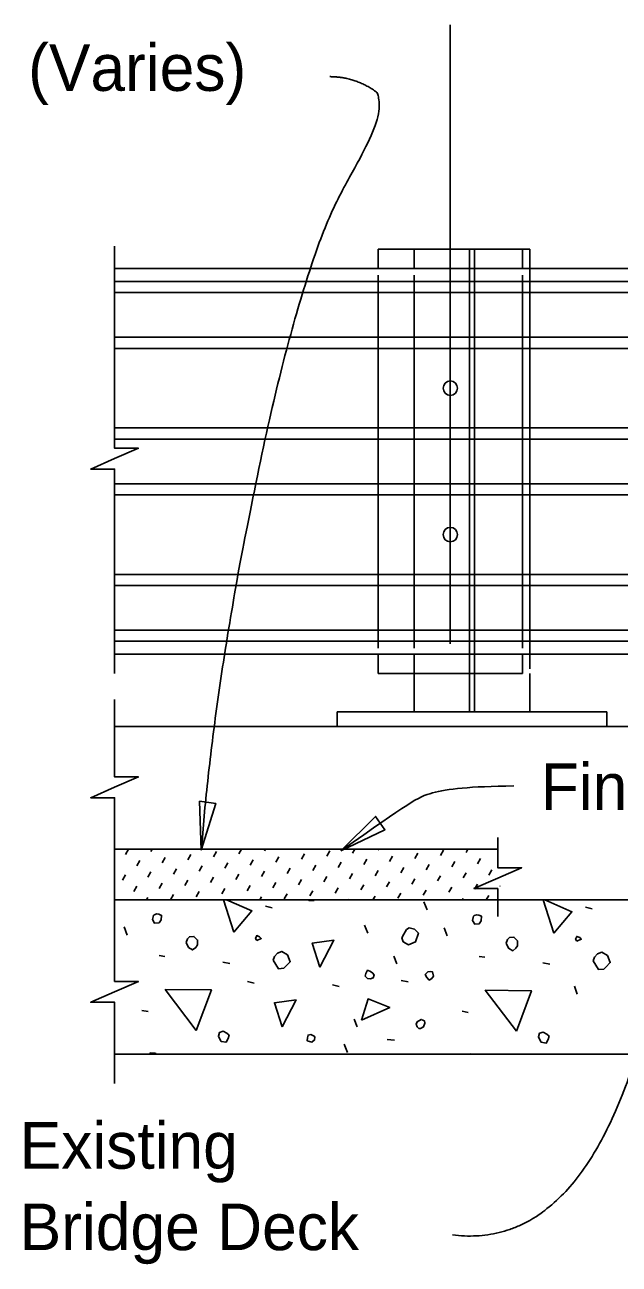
# Model space of a CAD drawing. Extents: x 21587 to 21656.3, y 56114 to 56157.2.
# Drawn here: x 21587.27 to 21589.85, y 56132.48 to 56137.83 of the extents above; entities that cross this region are included whole.
import ezdxf

# ---------------------------------------------------------------- set-up
doc = ezdxf.new("R2010")
doc.units = 0
for name, color, linetype in [('AdhocPoint_dp', 7, 'Continuous'), ('Border', 7, 'Continuous'), ('Patterning', 7, 'Continuous'), ('PlotBorder_dp', 7, 'Continuous'), ('SheetBorder_dp', 7, 'Continuous'), ('TextMisc', 7, 'Continuous')]:
    doc.layers.add(name, color=color, linetype=linetype)

msp = doc.modelspace()

# ---------------------------------------------------------------- linework, layer by layer
at = {"layer": 'AdhocPoint_dp'}
for p, q in [((21593.837, 56134.8009), (21587.6633, 56134.8009)), ((21589.3212, 56134.2699), (21587.6633, 56134.2699)), ((21587.6633, 56134.0511), (21593.837, 56134.0511)), ((21587.6633, 56133.3843), (21593.837, 56133.3843))]:
    msp.add_line(p, q, dxfattribs=at)
at = {"layer": 'Border'}
for p, q in [((21588.9596, 56136.8635), (21589.4596, 56136.8635)), ((21588.9596, 56136.8635), (21588.9596, 56136.7802)), ((21599.7592, 56136.7801), (21587.6633, 56136.7801)), ((21587.6633, 56136.7246), (21599.7592, 56136.7246)), ((21587.6633, 56136.6764), (21599.7592, 56136.6764)), ((21587.6633, 56136.4835), (21599.7592, 56136.4835)), ((21587.6633, 56136.4353), (21599.7592, 56136.4353)), ((21587.6633, 56136.0914), (21599.7592, 56136.0914)), ((21587.6633, 56136.0431), (21599.7592, 56136.0431)), ((21587.6633, 56135.8503), (21599.7592, 56135.8503)), ((21587.6633, 56135.8022), (21599.7592, 56135.8022)), ((21587.6633, 56135.4582), (21599.7592, 56135.4582)), ((21587.6633, 56135.41), (21599.7592, 56135.41)), ((21587.6633, 56135.2172), (21599.7592, 56135.2172)), ((21587.6633, 56135.169), (21599.7592, 56135.169)), ((21599.7592, 56135.1134), (21587.6633, 56135.1134)), ((21588.9596, 56135.1135), (21588.9596, 56134.8635)), ((21589.4596, 56135.0302), (21589.4596, 56134.8635)), ((21588.6263, 56134.8635), (21589.7929, 56134.8635)), ((21588.6263, 56134.801), (21588.6263, 56134.8635)), ((21588.9596, 56134.8635), (21589.4596, 56134.8635)), ((21589.7929, 56134.8635), (21589.7929, 56134.801)), ((21588.6263, 56134.801), (21589.7929, 56134.801))]:
    msp.add_line(p, q, dxfattribs=at)
for centre in [(21589.1159, 56136.2634), (21589.1159, 56135.6303)]:
    msp.add_circle(centre, 0.0312, dxfattribs=at)
at = {"layer": 'Patterning'}
for p, q in [((21589.1992, 56134.8635), (21589.1992, 56136.8635)), ((21589.22, 56134.8635), (21589.22, 56136.8635)), ((21589.4596, 56136.8635), (21589.4596, 56135.0505)), ((21588.9596, 56136.7516), (21588.9596, 56135.1398))]:
    msp.add_line(p, q, dxfattribs=at)
at = {"layer": 'PlotBorder_dp'}
msp.add_line((21589.1159, 56135.1581), (21589.1159, 56137.8341), dxfattribs=at)
for points in [[(21587.6633, 56135.0304), (21587.6633, 56135.9136), (21587.5599, 56135.9136), (21587.6633, 56135.9586), (21587.7666, 56136.0036), (21587.6633, 56136.0036), (21587.6633, 56136.8766)], [(21587.6633, 56134.023), (21587.6633, 56134.4931), (21587.5599, 56134.4931), (21587.6633, 56134.5381), (21587.7666, 56134.5831), (21587.6633, 56134.5831), (21587.6633, 56134.9176)], [(21589.3213, 56133.979), (21589.3213, 56134.0999), (21589.2179, 56134.0999), (21589.3213, 56134.1449), (21589.4246, 56134.1899), (21589.3213, 56134.1899), (21589.3213, 56134.3205)], [(21587.6633, 56133.2579), (21587.6633, 56133.6085), (21587.5599, 56133.6085), (21587.6633, 56133.6535), (21587.7666, 56133.6985), (21587.6633, 56133.6985), (21587.6633, 56134.023)]]:
    msp.add_lwpolyline(points, dxfattribs=at)
for points in [[(21588.0386, 56134.2665), (21588.1011, 56134.4682), (21588.0312, 56134.4775)], [(21588.6428, 56134.2633), (21588.8333, 56134.3544), (21588.7927, 56134.4121)]]:
    msp.add_lwpolyline(points, close=True, dxfattribs=at)
for points, degree in [([(21588.5944, 56137.6099), (21588.6936, 56137.6099), (21588.8704, 56137.4978), (21588.4823, 56136.8422), (21588.0942, 56134.9965), (21588.0386, 56134.2665)], 2), ([(21589.3913, 56134.5436), (21589.1979, 56134.5415), (21589.0095, 56134.5211), (21588.9381, 56134.4713), (21588.6427, 56134.2634)], 3), ([(21590.0017, 56133.6862), (21589.743, 56132.5258), (21589.1249, 56132.603)], 2)]:
    msp.add_open_spline(points, degree=degree, dxfattribs=at)
at = {"layer": 'TextMisc'}
for p, q in [((21588.8034, 56136.8635), (21589.4284, 56136.8635)), ((21588.8034, 56136.8635), (21588.8034, 56136.7802)), ((21589.4284, 56136.8635), (21589.4284, 56136.7802)), ((21588.8034, 56136.7516), (21588.8034, 56135.1398)), ((21589.4284, 56136.7516), (21589.4284, 56135.1398)), ((21588.8034, 56135.0302), (21588.8034, 56135.1135)), ((21589.4284, 56135.0302), (21589.4284, 56135.1135)), ((21588.8034, 56135.0302), (21589.4284, 56135.0302)), ((21587.7102, 56134.2474), (21587.7231, 56134.2698)), ((21587.8208, 56134.2604), (21587.8263, 56134.2699)), ((21587.9803, 56134.2245), (21587.9932, 56134.2469)), ((21588.0909, 56134.2375), (21588.1039, 56134.2599)), ((21588.2015, 56134.2504), (21588.2128, 56134.2699)), ((21588.3122, 56134.2634), (21588.3159, 56134.2699)), ((21588.4716, 56134.2275), (21588.4846, 56134.2499)), ((21588.5823, 56134.2405), (21588.5952, 56134.2629)), ((21588.6929, 56134.2535), (21588.7024, 56134.2699)), ((21588.8035, 56134.2664), (21588.8055, 56134.2699)), ((21588.963, 56134.2306), (21588.976, 56134.253)), ((21589.0736, 56134.2435), (21589.0866, 56134.2659)), ((21589.1843, 56134.2565), (21589.192, 56134.2699)), ((21589.2949, 56134.2695), (21589.2952, 56134.2699)), ((21587.759, 56134.1986), (21587.772, 56134.221)), ((21587.8696, 56134.2116), (21587.8826, 56134.234)), ((21588.0291, 56134.1757), (21588.0421, 56134.1981)), ((21588.1397, 56134.1887), (21588.1527, 56134.211)), ((21588.2504, 56134.2016), (21588.2633, 56134.224)), ((21588.361, 56134.2146), (21588.374, 56134.237)), ((21588.5205, 56134.1787), (21588.5334, 56134.2011)), ((21588.6311, 56134.1917), (21588.6441, 56134.2141)), ((21588.7417, 56134.2046), (21588.7547, 56134.227)), ((21588.8524, 56134.2176), (21588.8653, 56134.24)), ((21589.0118, 56134.1817), (21589.0248, 56134.2041)), ((21589.1225, 56134.1947), (21589.1354, 56134.2171)), ((21589.2331, 56134.2077), (21589.2461, 56134.23)), ((21587.6972, 56134.1368), (21587.7102, 56134.1592)), ((21587.8078, 56134.1498), (21587.8208, 56134.1722)), ((21587.9185, 56134.1627), (21587.9314, 56134.1851)), ((21588.0779, 56134.1269), (21588.0909, 56134.1492)), ((21588.1886, 56134.1398), (21588.2015, 56134.1622)), ((21588.2992, 56134.1528), (21588.3122, 56134.1752)), ((21588.4098, 56134.1657), (21588.4228, 56134.1881)), ((21588.4587, 56134.1169), (21588.4716, 56134.1393)), ((21588.5693, 56134.1299), (21588.5823, 56134.1523)), ((21588.6799, 56134.1428), (21588.6929, 56134.1652)), ((21588.7906, 56134.1558), (21588.8035, 56134.1782)), ((21588.9012, 56134.1688), (21588.9142, 56134.1912)), ((21588.95, 56134.1199), (21588.963, 56134.1423)), ((21589.0607, 56134.1329), (21589.0736, 56134.1553)), ((21589.1713, 56134.1459), (21589.1843, 56134.1682)), ((21589.2819, 56134.1588), (21589.2949, 56134.1812)), ((21587.746, 56134.088), (21587.759, 56134.1104)), ((21587.8567, 56134.1009), (21587.8696, 56134.1233)), ((21587.9673, 56134.1139), (21587.9803, 56134.1363)), ((21588.0161, 56134.0651), (21588.0291, 56134.0874)), ((21588.1268, 56134.078), (21588.1397, 56134.1004)), ((21588.2374, 56134.091), (21588.2504, 56134.1134)), ((21588.348, 56134.1039), (21588.361, 56134.1263)), ((21588.5075, 56134.0681), (21588.5205, 56134.0905)), ((21588.6181, 56134.081), (21588.6311, 56134.1034)), ((21588.7288, 56134.094), (21588.7417, 56134.1164)), ((21588.8394, 56134.107), (21588.8524, 56134.1294)), ((21588.9989, 56134.0711), (21589.0118, 56134.0935)), ((21589.1095, 56134.0841), (21589.1225, 56134.1065)), ((21589.2201, 56134.097), (21589.2331, 56134.1194)), ((21589.3308, 56134.11), (21589.3309, 56134.1102)), ((21587.8017, 56134.0509), (21587.8078, 56134.0615)), ((21587.9055, 56134.0521), (21587.9185, 56134.0745)), ((21588.1882, 56134.0509), (21588.1886, 56134.0516)), ((21588.2913, 56134.0509), (21588.2992, 56134.0645)), ((21588.3969, 56134.0551), (21588.4098, 56134.0775)), ((21588.6778, 56134.0509), (21588.6799, 56134.0546)), ((21588.7809, 56134.0509), (21588.7906, 56134.0676)), ((21588.8882, 56134.0581), (21588.9012, 56134.0805)), ((21589.0151, 56134.0079), (21589.001, 56134.0432)), ((21589.1674, 56134.0509), (21589.1713, 56134.0576)), ((21589.2706, 56134.0509), (21589.2819, 56134.0706)), ((21588.3168, 56134.0238), (21588.3451, 56134.0167)), ((21589.7015, 56134.0203), (21589.7298, 56134.0132)), ((21587.7182, 56133.8989), (21587.7041, 56133.9343)), ((21588.7588, 56133.9071), (21588.7446, 56133.9425)), ((21589.1029, 56133.8954), (21589.0887, 56133.9307)), ((21587.8561, 56133.8105), (21587.8808, 56133.807)), ((21588.1319, 56133.7822), (21588.1619, 56133.7769)), ((21588.8843, 56133.7745), (21588.8719, 56133.8081)), ((21589.2408, 56133.807), (21589.2655, 56133.8034)), ((21589.5165, 56133.7787), (21589.5466, 56133.7734)), ((21588.2388, 56133.6983), (21588.2671, 56133.6913)), ((21588.6068, 56133.6844), (21588.635, 56133.6773)), ((21588.9031, 56133.7027), (21588.9332, 56133.6974)), ((21589.665, 56133.6443), (21589.6526, 56133.6779)), ((21587.7818, 56133.5736), (21587.8083, 56133.5683)), ((21589.1665, 56133.5701), (21589.193, 56133.5648)), ((21588.7128, 56133.5018), (21588.7004, 56133.5354)), ((21588.843, 56133.4481), (21588.8748, 56133.4446)), ((21588.6704, 56133.3922), (21588.6563, 56133.4275))]:
    msp.add_line(p, q, dxfattribs=at)
for points in [[(21588.1796, 56133.9113), (21588.1341, 56134.0509)], [(21588.148, 56134.0509), (21588.2574, 56134.0032), (21588.1796, 56133.9113)], [(21588.5032, 56134.0509), (21588.5042, 56134.0485), (21588.5018, 56134.0509)], [(21588.5042, 56134.0485), (21588.5254, 56134.0485), (21588.5278, 56134.0509)], [(21589.5643, 56133.9077), (21589.5177, 56134.0509)], [(21589.5246, 56134.0509), (21589.642, 56133.9997), (21589.5643, 56133.9077)], [(21587.8278, 56133.9661), (21587.8366, 56133.9502), (21587.8561, 56133.9519), (21587.8649, 56133.9643), (21587.8667, 56133.9838), (21587.8543, 56133.9891), (21587.8455, 56133.9908), (21587.8349, 56133.9873), (21587.8313, 56133.9838), (21587.8278, 56133.9661)], [(21589.2125, 56133.9625), (21589.2213, 56133.9466), (21589.2408, 56133.9484), (21589.2496, 56133.9608), (21589.2514, 56133.9802), (21589.239, 56133.9855), (21589.2302, 56133.9873), (21589.2195, 56133.9838), (21589.216, 56133.9802), (21589.2125, 56133.9625)], [(21588.9126, 56133.87), (21588.9356, 56133.8576), (21588.9656, 56133.87), (21588.978, 56133.9071), (21588.9603, 56133.9248), (21588.9373, 56133.9301), (21588.9267, 56133.923), (21588.9143, 56133.9036), (21588.9055, 56133.8877), (21588.9126, 56133.87)], [(21587.9728, 56133.8671), (21587.9834, 56133.8459), (21588.001, 56133.8353), (21588.0152, 56133.8459), (21588.0222, 56133.8565), (21588.0222, 56133.8777), (21588.0063, 56133.8936), (21587.9869, 56133.8918), (21587.9781, 56133.883), (21587.9728, 56133.8671)], [(21588.2786, 56133.8759), (21588.298, 56133.8848), (21588.291, 56133.8918), (21588.2786, 56133.8971), (21588.2733, 56133.8848), (21588.2786, 56133.8759)], [(21588.552, 56133.7604), (21588.5184, 56133.8647), (21588.6121, 56133.8771), (21588.552, 56133.7604)], [(21589.3574, 56133.8635), (21589.368, 56133.8423), (21589.3857, 56133.8317), (21589.3999, 56133.8423), (21589.4069, 56133.8529), (21589.4069, 56133.8742), (21589.391, 56133.8901), (21589.3716, 56133.8883), (21589.3627, 56133.8795), (21589.3574, 56133.8635)], [(21589.6633, 56133.8724), (21589.6827, 56133.8812), (21589.6756, 56133.8883), (21589.6633, 56133.8936), (21589.6579, 56133.8812), (21589.6633, 56133.8724)], [(21588.3493, 56133.7911), (21588.3723, 56133.7539), (21588.3952, 56133.7557), (21588.4041, 56133.7646), (21588.4235, 56133.784), (21588.4112, 56133.814), (21588.3864, 56133.8282), (21588.3687, 56133.8211), (21588.3546, 56133.807), (21588.3493, 56133.7911)], [(21589.734, 56133.7875), (21589.7569, 56133.7504), (21589.7799, 56133.7522), (21589.7888, 56133.761), (21589.8082, 56133.7805), (21589.7958, 56133.8105), (21589.7711, 56133.8247), (21589.7534, 56133.8176), (21589.7393, 56133.8034), (21589.734, 56133.7875)], [(21588.7577, 56133.7114), (21588.7701, 56133.7096), (21588.7824, 56133.7149), (21588.786, 56133.7256), (21588.7807, 56133.7344), (21588.7701, 56133.7415), (21588.7577, 56133.7468), (21588.7506, 56133.7326), (21588.7471, 56133.722), (21588.7577, 56133.7114)], [(21589.0145, 56133.7151), (21589.0251, 56133.7044), (21589.0357, 56133.7115), (21589.0428, 56133.7221), (21589.0392, 56133.7398), (21589.0304, 56133.7416), (21589.018, 56133.7398), (21589.0074, 56133.7292), (21589.0145, 56133.7151)], [(21588.0169, 56133.487), (21587.8826, 56133.6638), (21588.0824, 56133.662), (21588.0169, 56133.487)], [(21589.4016, 56133.4835), (21589.2673, 56133.6603), (21589.467, 56133.6585), (21589.4016, 56133.4835)], [(21588.3887, 56133.5022), (21588.3551, 56133.6065), (21588.4488, 56133.6188), (21588.3887, 56133.5022)], [(21588.7316, 56133.5312), (21588.7599, 56133.6231), (21588.8536, 56133.586), (21588.7316, 56133.5312)], [(21588.9791, 56133.4959), (21588.9862, 56133.4959), (21589.0003, 56133.5029), (21589.0056, 56133.5188), (21589.0039, 56133.5277), (21588.9897, 56133.5347), (21588.9721, 56133.5241), (21588.9685, 56133.5135), (21588.9721, 56133.5029), (21588.9791, 56133.4959)], [(21588.1159, 56133.4552), (21588.1248, 56133.4393), (21588.146, 56133.4357), (21588.1548, 56133.4517), (21588.1584, 56133.4658), (21588.1495, 56133.4746), (21588.1336, 56133.4835), (21588.1177, 56133.4782), (21588.1124, 56133.4623), (21588.1159, 56133.4552)], [(21588.4968, 56133.4422), (21588.5163, 56133.4369), (21588.5286, 56133.4457), (21588.5304, 56133.4581), (21588.5269, 56133.4617), (21588.5127, 56133.4687), (21588.5003, 56133.467), (21588.4986, 56133.4546), (21588.4968, 56133.4422)], [(21589.5006, 56133.4517), (21589.5095, 56133.4357), (21589.5307, 56133.4322), (21589.5395, 56133.4481), (21589.543, 56133.4623), (21589.5342, 56133.4711), (21589.5183, 56133.4799), (21589.5024, 56133.4746), (21589.4971, 56133.4587), (21589.5006, 56133.4517)], [(21587.8412, 56133.3843), (21587.8402, 56133.388), (21587.8172, 56133.3898), (21587.8154, 56133.3843)], [(21589.2249, 56133.3843), (21589.2248, 56133.3845), (21589.2019, 56133.3862), (21589.2012, 56133.3843)]]:
    msp.add_lwpolyline(points, dxfattribs=at)

# ---------------------------------------------------------------- texts
at = {"layer": 'PlotBorder_dp'}
for s, p in [('(Varies)', (21587.2893, 56137.5484)), ('Existing ', (21587.2526, 56132.8891)), ('Bridge Deck', (21587.2526, 56132.5371))]:
    msp.add_text(s, height=0.2016, dxfattribs=at).set_placement(p)
at = {"layer": 'SheetBorder_dp'}
msp.add_text('Final Riding Surface', height=0.2016, dxfattribs=at).set_placement((21589.5074, 56134.4399))

doc.saveas('drawing.dxf')
